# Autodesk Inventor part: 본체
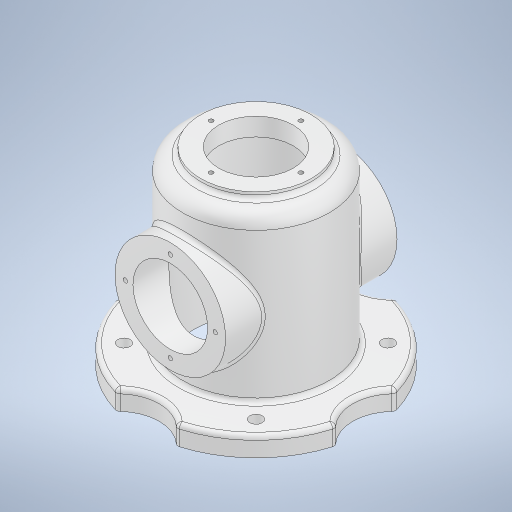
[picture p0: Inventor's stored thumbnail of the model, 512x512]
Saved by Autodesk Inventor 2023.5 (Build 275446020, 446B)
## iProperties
Created: 2026-07
Part Number: 본체
Material: 알루미늄 6061
Document SubType Name: Modeling
Designer: mirae
Mass: 1505.49 g
Surface Area: 1247.94 cm^2
Volume: 557.587 cm^3
Density: 2.7 g/cm^3
Appearance: 알루미늄 - 평지
Author: mirae
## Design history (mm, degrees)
sketch "스케치1"
  geometry: L1 (0, 0)-(0, -55.788); L2 (0, 0)-(37.571, 0); C1 r 30 at (-100, 0); A1 r 30 centre (100, 0) between (79.12, -21.541) and (79.12, 21.541); A2 r 30 centre (0, -100) between (-21.541, -79.12) and (21.541, -79.12); A3 r 82 centre (0, 0) between (21.541, -79.12) and (79.12, -21.541); A4 r 30 centre (0, 100) between (21.541, 79.12) and (-21.541, 79.12); A5 r 82 centre (0, 0) between (79.12, 21.541) and (21.541, 79.12); A6 r 82 centre (0, 0) between (-21.541, 79.12) and (-21.541, -79.12); 3 further points
  constraints: 12 point on circle, 7 centre point, 4 end point, 2 symmetric about line, 1 coincident, 1 horizontal, 1 horizontal alignment, 1 point on line, 1 vertical, 2 other
  dimensions: "d1" = 60 diameter of A1; "d3" = 100 distance of point (0, 0) A1.centre; "d4" = 60 diameter of A2; "d5" = 100 distance of point (0, 0) A2.centre; "d7" = 82 radius of A3; "d8" = 82 radius of A6; "d9" = 82 radius of A5
extrude "돌출1" new body sketch "스케치1" distance "d10" = 14; taper "d11" = 0 deg
sketch "스케치2"
  geometry: C1 r 53 at (0, 0); 1 further point
  constraints: 1 centre point, 1 coincident
  dimensions: "d12" = 106 diameter of C1
extrude "돌출2" join sketch "스케치2" distance "d13" = 132; taper "d14" = 0 deg
sketch "스케치3"
  geometry: C1 r 40 at (0, 0); 1 further point
  constraints: 1 centre point, 1 coincident
  dimensions: "d15" = 80 diameter of C1
extrude "돌출3" join sketch "스케치3" distance "d16" = 5; taper "d17" = 0 deg
node "작업 평면1"
sketch "스케치4"
  geometry: L1 (53, 132)-(-53, 132) reference; L2 (-53, 14)-(53, 14) reference; L3 (53, 14)-(53, 132) reference; L4 (-21.541, 0)-(21.541, 0) reference; C1 r 40 at (0, 68); 2 further points
  constraints: 1 centre point, 1 midpoint, 1 vertical alignment
  dimensions: "d19" = 80 diameter of C1; "d20" = 68 distance from line of L4 C1.centre
extrude "돌출4" join sketch "스케치4" stored distance "d21" = 5; taper "d22" = 0 deg
sketch "스케치5"
  geometry: L1 (0, 0)-(14.926, 0); L2 (0, 0)-(0, 16.586); C1 r 40 at (0, 0) reference; A1 r 32.5 centre (0, 0) between (0, 32.5) and (32.5, 0); 3 further points
  constraints: 4 end point, 4 point on circle, 2 horizontal alignment, 2 vertical alignment, 1 centre point, 1 coincident, 1 horizontal, 1 vertical
  dimensions: "d23" = 65 diameter of A1
hole "구멍1" sketch "스케치5" at (0, 32.5), (32.5, 0), (0, -32.5), (-32.5, 0) diameter "d24" = 3.242; stored, may be unused: countersink angle "d28" = 90 deg, drill point angle "d30" = 118 deg; dims "d25" = 8, "d26" = 4, "d27" = 2, "d29" = 10
sketch "스케치6"
  geometry: C1 r 1.621 at (0, -32.5) reference; C2 r 1.621 at (0, 32.5) reference; C3 r 1.621 at (32.5, 0) reference; C4 r 1.621 at (-32.5, 0) reference; C5 r 40 at (0, 0) reference; C6 r 27 at (0, 0); 1 further point
  constraints: 1 centre point, 1 coincident
  dimensions: "d31" = 54 diameter of C6
extrude "돌출5" cut sketch "스케치6" extent not by distance; stored distance "d32" = 0; taper "d33" = 0 deg
sketch "스케치7"
  geometry: C1 r 27 at (0, 0); 1 further point
  constraints: 1 centre point, 1 coincident
  dimensions: "d34" = 54 diameter of C1
extrude "돌출6" cut sketch "스케치7" extent not by distance; stored distance "d35" = 0; taper "d36" = 0 deg
sketch "스케치8"
  geometry: A1 r 32.5 centre (0, 0) between (-32.5, 0) and (0, 32.5); 3 further points
  constraints: 4 point on circle, 2 horizontal alignment, 2 vertical alignment, 1 centre point, 1 coincident
  dimensions: "d37" = 65 diameter of A1
hole "구멍2" sketch "스케치8" at (-32.5, 0), (0, 32.5), (32.5, 0), (0, -32.5) diameter "d38" = 3.242; stored, may be unused: countersink angle "d42" = 90 deg, drill point angle "d44" = 118 deg; dims "d39" = 8, "d40" = 4, "d41" = 2, "d43" = 10
sketch "스케치9"
  geometry: L1 (0, 0)-(-105.357, 0); L2 (0, 0)-(0, 121.247); L3 (0, 0)-(-39.781, 39.781); L4 (0, 0)-(-35.731, -35.731); L5 (0, 0)-(33.645, -33.645); L6 (0, 0)-(37.744, 37.744); A1 r 67.5 centre (0, 0) between (-47.73, -47.73) and (-47.73, 47.73); 3 further points
  constraints: 12 end point, 4 point on circle, 4 point on line, 1 centre point, 1 coincident, 1 horizontal, 1 perpendicular, 1 vertical
  dimensions: "d45" = 135 diameter of A1; "d46" = 45 deg angle of L3 L2; "d47" = 90 deg angle of L4 L3; "d48" = 90 deg angle of L6 L5
hole "구멍3" sketch "스케치9" at (-47.73, -47.73), (-47.73, 47.73), (47.73, 47.73), (47.73, -47.73) diameter "d49" = 9; stored, may be unused: countersink angle "d53" = 90 deg, drill point angle "d55" = 118 deg; dims "d50" = 6, "d51" = 4, "d52" = 2, "d54" = 8
fillet "모깎기1" dims "d56" = 10
fillet "모깎기2" dims "d57" = 3
fillet "모깎기3" dims "d58" = 3
sketch "스케치10"
  geometry: C1 r 45 at (0, 0); 1 further point
  constraints: 1 centre point, 1 coincident
  dimensions: "d59" = 90 diameter of C1
extrude "돌출7" cut sketch "스케치10" distance "d60" = 124; taper "d61" = 0 deg
fillet "모깎기4" dims "d62" = 3
node "작업 평면2"
sketch "스케치11"
  geometry: L1 (0, -20.357)-(0, 20.357) reference; 4 further points
  constraints: 2 midpoint, 1 horizontal alignment, 1 other
  dimensions: "d63" = 70 distance of point (-70, 0) point (0, 0)
feature "엠보싱1" sketch "스케치11" dims "d64" = 0.5, "d65" = 0
fillet "모깎기5" dims "d66" = 3
node "솔리드1"
mirror "미러1"
node "투영된 루프1"
node "투영된 루프2"
node "투영된 루프3"
feature "A9D066F2-1C7D-4E18-AEED-F7BC21143FA4" dims "d49" = 9, "d50" = 6, "d51" = 4, "d52" = 2, "d53" = 90 deg, "d54" = 8, "d55" = 118 deg
other parameters: "d0" = 164, "d6" = 82, "d18" = 62
